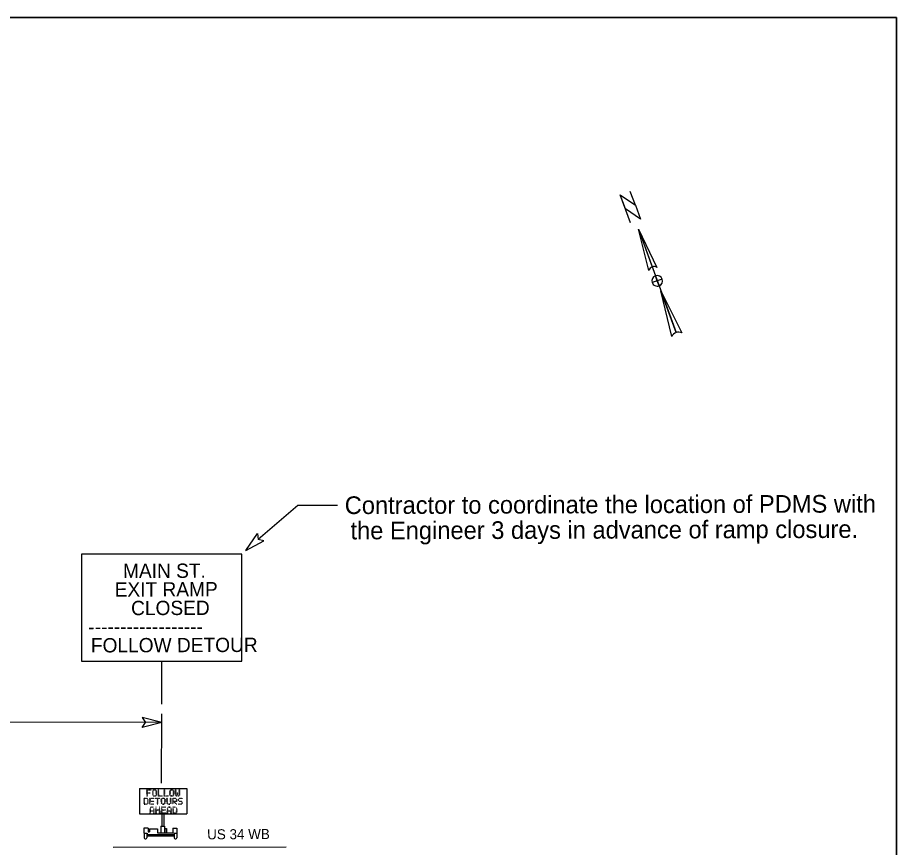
# Model space of a CAD drawing. Extents: x 10133 to 81668, y 6132 to 11018.
# Drawn here: x 12392 to 13268, y 9117 to 9944 of the extents above; entities that cross this region are included whole.
import ezdxf

# ---------------------------------------------------------------- set-up
doc = ezdxf.new("R2010")
doc.units = 0
for name, color, linetype in [('dsnTextFinalPlan', 7, 'Continuous'), ('Level 10', 7, 'Continuous'), ('Level 2', 7, 'Continuous'), ('Level 9', 7, 'Continuous'), ('SheetBorder', 7, 'Continuous'), ('SheetText', 7, 'Continuous')]:
    doc.layers.add(name, color=color, linetype=linetype)

msp = doc.modelspace()

# ---------------------------------------------------------------- linework, layer by layer
at = {"layer": 'dsnTextFinalPlan'}
for p, q in [((13010.55, 9733.35), (13028.98, 9695.11)), ((13010.55, 9733.35), (13048.16, 9630.16)), ((13021.05, 9692.22), (13021.05, 9692.22)), ((13021.07, 9692.64), (13021.5, 9693.74)), ((13031.16, 9676.79), (13031.16, 9676.79)), ((13043.92, 9626.36), (13032.97, 9671.83)), ((12536.05, 9260.06), (12536.05, 9302.79)), ((12535.88, 9181.22), (12536.04, 9250.46)), ((12536.02, 9241.73), (12162.39, 9242.64)), ((12487.48, 9117.49), (12659.77, 9117.91))]:
    msp.add_line(p, q, dxfattribs=at)
for points in [[(13002.7, 9739.48), (12992.57, 9767.27), (13007.56, 9756.99), (13002.49, 9770.88)], [(13021.05, 9692.22), (13010.55, 9733.35), (13024.29, 9695.65)], [(13031.16, 9676.79), (13029.35, 9681.76), (13024.39, 9679.95)], [(13034.32, 9683.56), (13029.35, 9681.76), (13027.55, 9686.72)], [(13048.16, 9630.16), (13032.97, 9671.83), (13053.84, 9629.98)], [(12711.12, 9457.97), (12671.64, 9457.97), (12632.06, 9424.18)], [(12619.85, 9413.25), (12631.24, 9429.95), (12632.06, 9424.18)], [(12619.85, 9413.25), (12637.71, 9422.72), (12632.06, 9424.18)], [(12536.02, 9241.73), (12516.38, 9236.93), (12519.64, 9241.77)], [(12536.02, 9241.73), (12516.41, 9246.63), (12519.64, 9241.77)]]:
    msp.add_lwpolyline(points, dxfattribs=at)
for points in [[(13012.62, 9743.1), (12997.63, 9753.38), (12992.57, 9767.27), (13007.56, 9756.99)], [(12615.87, 9409.47), (12456.22, 9409.47), (12456.22, 9302.79), (12615.87, 9302.79)]]:
    msp.add_lwpolyline(points, close=True, dxfattribs=at)
for centre, radius, start, end in [((13026.1, 9690.69), 5.28, 110.04376, 163.14911), ((13026.1, 9690.69), 5.28, 56.87143, 110.04521), ((13029.35, 9681.76), 5.28, 110.02337, 200.02337), ((13029.35, 9681.76), 5.28, 200.02337, 290.02337), ((13029.35, 9681.76), 5.28, 20.02337, 110.02337), ((13029.35, 9681.76), 5.28, 290.02337, 20.02337), ((13050.78, 9622.97), 7.65, 110.01276, 153.64232), ((13050.78, 9622.96), 7.66, 66.42543, 110.02402)]:
    msp.add_arc(centre, radius, start, end, dxfattribs=at)
at = {"layer": 'Level 10'}
msp.add_lwpolyline([(12615.87, 9409.47), (12456.22, 9409.47), (12456.22, 9302.79), (12615.87, 9302.79)], close=True, dxfattribs=at)
at = {"layer": 'Level 9'}
for p, q in [((12513.87, 9176.08), (12513.87, 9150.64)), ((12513.87, 9176.08), (12560.98, 9176.08)), ((12560.98, 9176.08), (12560.98, 9150.64)), ((12513.87, 9150.64), (12560.98, 9150.64)), ((12536.17, 9150.64), (12536.17, 9138.45)), ((12537.88, 9150.64), (12537.88, 9138.45)), ((12522.36, 9136.37), (12518.27, 9136.37)), ((12518.27, 9136.37), (12518.27, 9132.07)), ((12522.36, 9136.37), (12522.36, 9132.86)), ((12535.09, 9138.45), (12538.82, 9138.45)), ((12535.09, 9138.45), (12535.09, 9132.04)), ((12538.82, 9138.45), (12538.82, 9132.04)), ((12547, 9136.37), (12547, 9132.04)), ((12547, 9136.37), (12551.08, 9136.37)), ((12551.08, 9136.37), (12551.08, 9131.59)), ((12518.27, 9132.07), (12518.27, 9131.59)), ((12518.27, 9131.59), (12521.5, 9131.59)), ((12518.43, 9131.59), (12518.43, 9126.88)), ((12521.06, 9131.59), (12521.06, 9126.88)), ((12521.06, 9129.5), (12548.31, 9129.5)), ((12521.06, 9128.77), (12548.31, 9128.77)), ((12521.5, 9131.59), (12521.5, 9130.29)), ((12521.5, 9130.29), (12547.86, 9130.29)), ((12522.36, 9132.86), (12523.77, 9132.86)), ((12523.77, 9136.01), (12523.77, 9132.86)), ((12531.69, 9132.04), (12547, 9132.04)), ((12547.86, 9131.59), (12547.86, 9130.29)), ((12548.31, 9131.59), (12548.31, 9126.88)), ((12550.94, 9131.59), (12550.94, 9126.88)), ((12519.33, 9125.99), (12520.16, 9125.99)), ((12549.21, 9125.99), (12550.04, 9125.99))]:
    msp.add_line(p, q, dxfattribs=at)
for points in [[(12539.5, 9132.04), (12539.5, 9136.26), (12540.8, 9136.26), (12540.8, 9132.04)], [(12523.77, 9136.01), (12531.69, 9136.01), (12531.69, 9132.04)], [(12547.86, 9131.59), (12551.08, 9131.59)]]:
    msp.add_lwpolyline(points, dxfattribs=at)
for centre in [(12521.38, 9174.56), (12521.38, 9173.59), (12521.38, 9172.61), (12521.38, 9171.64), (12522.28, 9174.56), (12522.28, 9171.64), (12523.18, 9174.56), (12523.18, 9171.64), (12524.08, 9174.56), (12524.08, 9171.64), (12524.98, 9174.56), (12527.08, 9173.59), (12527.08, 9172.61), (12527.08, 9171.64), (12527.98, 9174.56), (12528.88, 9174.56), (12529.78, 9174.56), (12530.68, 9173.59), (12530.68, 9172.61), (12530.68, 9171.64), (12532.78, 9174.56), (12532.78, 9173.59), (12532.78, 9172.61), (12532.78, 9171.64), (12538.48, 9174.56), (12538.48, 9173.59), (12538.48, 9172.61), (12538.48, 9171.64), (12544.18, 9173.59), (12544.18, 9172.61), (12544.18, 9171.64), (12545.08, 9174.56), (12545.98, 9174.56), (12546.88, 9174.56), (12547.78, 9173.59), (12547.78, 9172.61), (12547.78, 9171.64), (12549.88, 9174.56), (12549.88, 9173.59), (12549.88, 9172.61), (12549.88, 9171.64), (12551.68, 9171.64), (12553.48, 9174.56), (12553.48, 9173.59), (12553.48, 9172.61), (12553.48, 9171.64), (12518.5, 9166.28), (12518.5, 9165.31), (12518.5, 9164.33), (12518.5, 9163.36), (12518.5, 9162.38), (12519.4, 9166.28), (12520.3, 9166.28), (12521.2, 9166.28), (12521.38, 9170.66), (12521.38, 9169.69), (12521.38, 9168.71), (12522.1, 9165.31), (12522.1, 9164.33), (12522.1, 9163.36), (12522.1, 9162.38), (12524.2, 9166.28), (12524.2, 9165.31), (12524.2, 9164.33), (12524.2, 9163.36), (12524.2, 9162.38), (12525.1, 9166.28), (12525.1, 9163.36), (12526, 9166.28), (12526, 9163.36), (12526.9, 9166.28), (12526.9, 9163.36), (12527.08, 9170.66), (12527.08, 9169.69), (12527.8, 9166.28), (12527.8, 9163.36), (12527.98, 9168.71), (12528.88, 9168.71), (12529.78, 9168.71), (12529.9, 9166.28), (12530.68, 9170.66), (12530.68, 9169.69), (12530.8, 9166.28), (12531.7, 9166.28), (12531.7, 9165.31), (12531.7, 9164.33), (12531.7, 9163.36), (12531.7, 9162.38), (12532.6, 9166.28), (12532.78, 9170.66), (12532.78, 9169.69), (12532.78, 9168.71), (12533.5, 9166.28), (12533.68, 9168.71), (12534.58, 9168.71), (12535.48, 9168.71), (12535.6, 9165.31), (12535.6, 9164.33), (12535.6, 9163.36), (12535.6, 9162.38), (12536.38, 9168.71), (12536.5, 9166.28), (12537.4, 9166.28), (12538.3, 9166.28), (12538.48, 9170.66), (12538.48, 9169.69), (12538.48, 9168.71), (12539.2, 9165.31), (12539.2, 9164.33), (12539.2, 9163.36), (12539.2, 9162.38), (12539.38, 9168.71), (12540.28, 9168.71), (12541.18, 9168.71), (12541.3, 9166.28), (12541.3, 9165.31), (12541.3, 9164.33), (12541.3, 9163.36), (12541.3, 9162.38), (12542.08, 9168.71), (12544.18, 9170.66), (12544.18, 9169.69), (12544.9, 9166.28), (12544.9, 9165.31), (12544.9, 9164.33), (12544.9, 9163.36), (12544.9, 9162.38), (12545.08, 9168.71), (12545.98, 9168.71), (12546.88, 9168.71), (12547, 9166.28), (12547, 9165.31), (12547, 9164.33), (12547, 9163.36), (12547, 9162.38), (12547.78, 9170.66), (12547.78, 9169.69), (12547.9, 9166.28), (12547.9, 9163.36), (12548.8, 9166.28), (12548.8, 9163.36), (12548.8, 9162.38), (12549.7, 9166.28), (12549.7, 9163.36), (12549.88, 9170.66), (12549.88, 9169.69), (12550.6, 9165.31), (12550.6, 9164.33), (12550.6, 9163.36), (12550.78, 9168.71), (12551.68, 9170.66), (12551.68, 9169.69), (12552.58, 9168.71), (12552.7, 9165.31), (12552.7, 9164.33), (12553.48, 9170.66), (12553.48, 9169.69), (12553.6, 9166.28), (12553.6, 9163.36), (12554.5, 9166.28), (12554.5, 9163.36), (12555.4, 9166.28), (12555.4, 9163.36), (12556.3, 9166.28), (12556.3, 9162.38), (12518.5, 9161.41), (12518.5, 9160.43), (12519.4, 9160.43), (12520.3, 9160.43), (12521.2, 9160.43), (12522.1, 9161.41), (12524.2, 9161.41), (12524.2, 9160.43), (12524.49, 9156.46), (12524.49, 9155.48), (12524.49, 9154.51), (12525.1, 9160.43), (12525.39, 9157.43), (12526, 9160.43), (12526.29, 9157.43), (12526.9, 9160.43), (12527.19, 9157.43), (12527.8, 9160.43), (12528.09, 9156.46), (12528.09, 9155.48), (12528.09, 9154.51), (12530.19, 9157.43), (12530.19, 9156.46), (12530.19, 9155.48), (12530.19, 9154.51), (12531.09, 9154.51), (12531.7, 9161.41), (12531.7, 9160.43), (12531.99, 9154.51), (12532.89, 9154.51), (12533.79, 9157.43), (12533.79, 9156.46), (12533.79, 9155.48), (12533.79, 9154.51), (12535.6, 9161.41), (12535.89, 9157.43), (12535.89, 9156.46), (12535.89, 9155.48), (12535.89, 9154.51), (12536.5, 9160.43), (12536.79, 9157.43), (12536.79, 9154.51), (12537.4, 9160.43), (12537.69, 9157.43), (12537.69, 9154.51), (12538.3, 9160.43), (12538.59, 9157.43), (12538.59, 9154.51), (12539.2, 9161.41), (12539.49, 9157.43), (12539.49, 9154.51), (12541.3, 9161.41), (12541.59, 9156.46), (12541.59, 9155.48), (12541.59, 9154.51), (12542.2, 9160.43), (12542.49, 9157.43), (12543.1, 9160.43), (12543.39, 9157.43), (12544, 9160.43), (12544.29, 9157.43), (12544.9, 9161.41), (12545.19, 9156.46), (12545.19, 9155.48), (12545.19, 9154.51), (12547, 9161.41), (12547, 9160.43), (12547.29, 9157.43), (12547.29, 9156.46), (12547.29, 9155.48), (12547.29, 9154.51), (12548.19, 9157.43), (12549.09, 9157.43), (12549.7, 9161.41), (12549.99, 9157.43), (12550.6, 9160.43), (12550.89, 9156.46), (12550.89, 9155.48), (12550.89, 9154.51), (12552.7, 9160.43), (12553.6, 9160.43), (12554.5, 9160.43), (12555.4, 9160.43), (12556.3, 9161.41), (12524.49, 9153.53), (12524.49, 9152.56), (12524.49, 9151.58), (12525.39, 9153.53), (12526.29, 9153.53), (12527.19, 9153.53), (12528.09, 9153.53), (12528.09, 9152.56), (12528.09, 9151.58), (12530.19, 9153.53), (12530.19, 9152.56), (12530.19, 9151.58), (12533.79, 9153.53), (12533.79, 9152.56), (12533.79, 9151.58), (12535.89, 9153.53), (12535.89, 9152.56), (12535.89, 9151.58), (12536.79, 9151.58), (12537.69, 9151.58), (12538.59, 9151.58), (12539.49, 9151.58), (12541.59, 9153.53), (12541.59, 9152.56), (12541.59, 9151.58), (12542.49, 9153.53), (12543.39, 9153.53), (12544.29, 9153.53), (12545.19, 9153.53), (12545.19, 9152.56), (12545.19, 9151.58), (12547.29, 9153.53), (12547.29, 9152.56), (12547.29, 9151.58), (12548.19, 9151.58), (12549.09, 9151.58), (12549.99, 9151.58), (12550.89, 9153.53), (12550.89, 9152.56)]:
    msp.add_circle(centre, 0.15, dxfattribs=at)
for centre, major_axis, start_param, end_param in [((12519.33, 9126.88), (-0.895, 0), 0, 1.570796), ((12520.16, 9126.88), (0.895, 0), 4.712389, 6.283185), ((12549.21, 9126.88), (-0.895, 0), 0, 1.570796), ((12550.04, 9126.88), (0.895, 0), 4.712389, 6.283185)]:
    msp.add_ellipse(centre, major_axis=major_axis, ratio=0.989241, start_param=start_param, end_param=end_param, dxfattribs=at)
at = {"layer": 'SheetBorder'}
msp.add_lwpolyline([(10132.52, 9944.02), (13267.53, 9944.02), (13267.53, 7924.02), (10132.52, 7924.02)], close=True, dxfattribs=at)
at = {"layer": 'SheetText'}
msp.add_lwpolyline([(10132.52, 9944.02), (10132.52, 7924.02), (13267.53, 7924.02), (13267.53, 9944.02)], close=True, dxfattribs=at)

# ---------------------------------------------------------------- texts
at = {"layer": 'dsnTextFinalPlan'}
for s, height, p in [('Contractor to coordinate the location of PDMS with', 17.6158, (12718.19, 9449.42)), ('the Engineer 3 days in advance of ramp closure.', 17.6158, (12723.94, 9424.2)), ('MAIN ST.', 14.238, (12497.41, 9385.69)), ('EXIT RAMP', 14.238, (12489.1, 9367.16)), ('CLOSED', 14.238, (12505.45, 9348.7)), ('------------------', 14.2383, (12462.83, 9330.06)), ('FOLLOW DETOUR', 14.2383, (12465.42, 9311.56))]:
    msp.add_text(s, height=height, rotation=0.17024, dxfattribs=at).set_placement(p)
at = {"layer": 'Level 2'}
msp.add_text('US 34 WB', height=10, rotation=0.34795, dxfattribs=at).set_placement((12581.19, 9125.35))

doc.saveas('drawing.dxf')
